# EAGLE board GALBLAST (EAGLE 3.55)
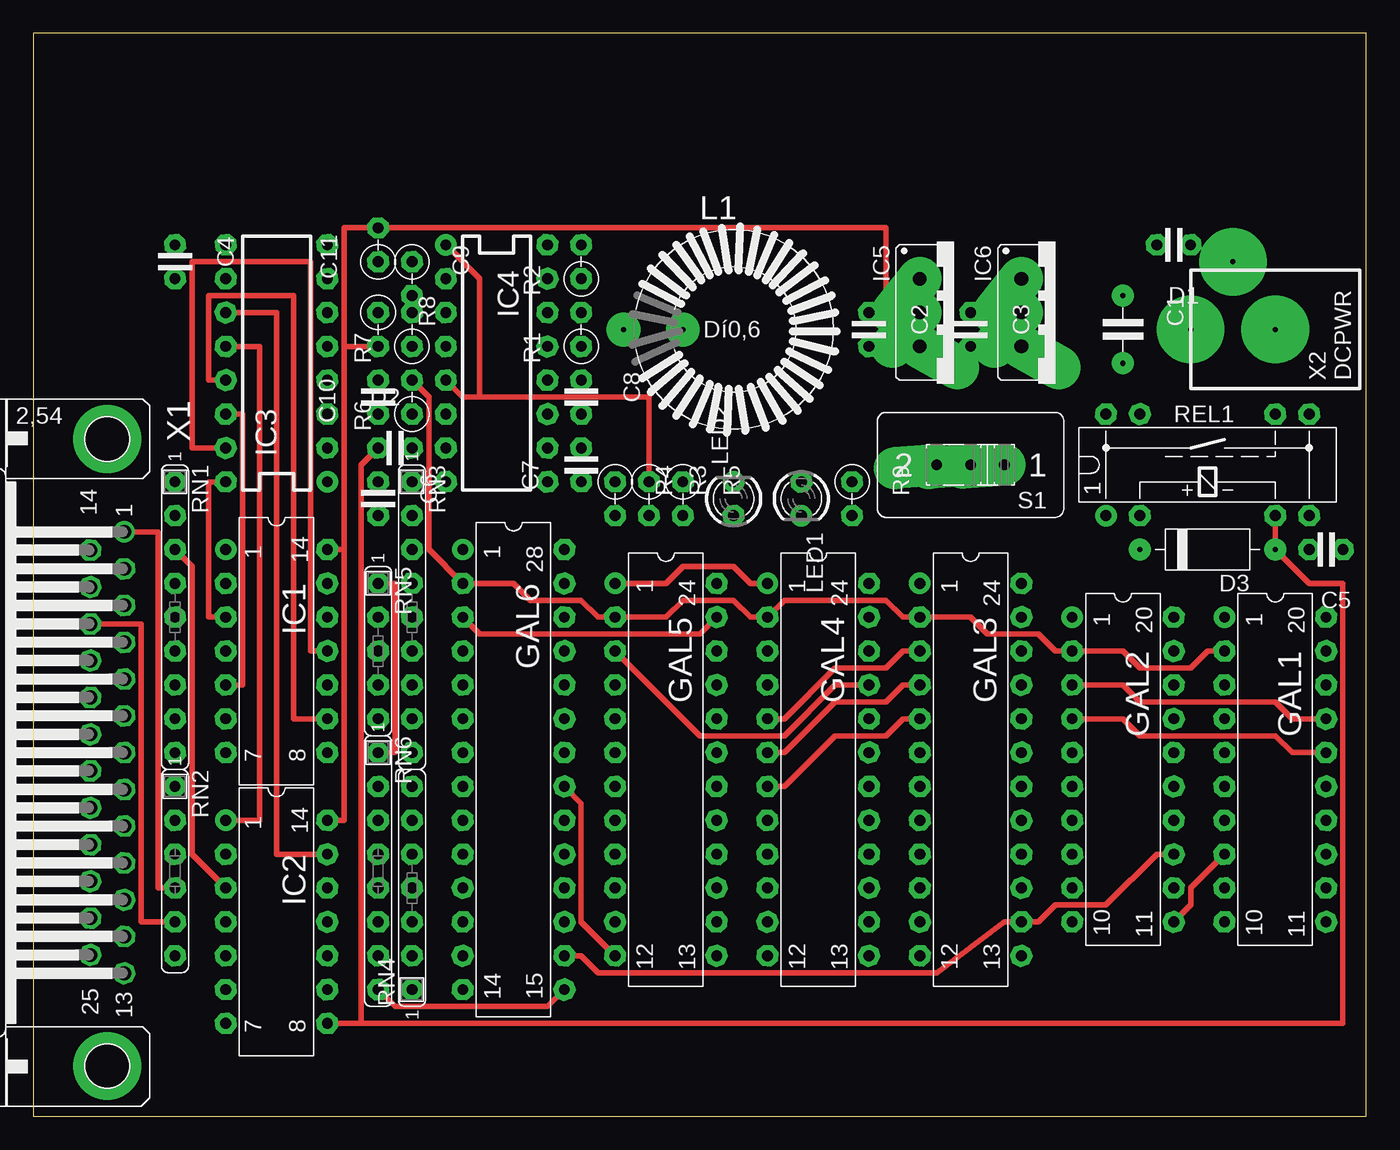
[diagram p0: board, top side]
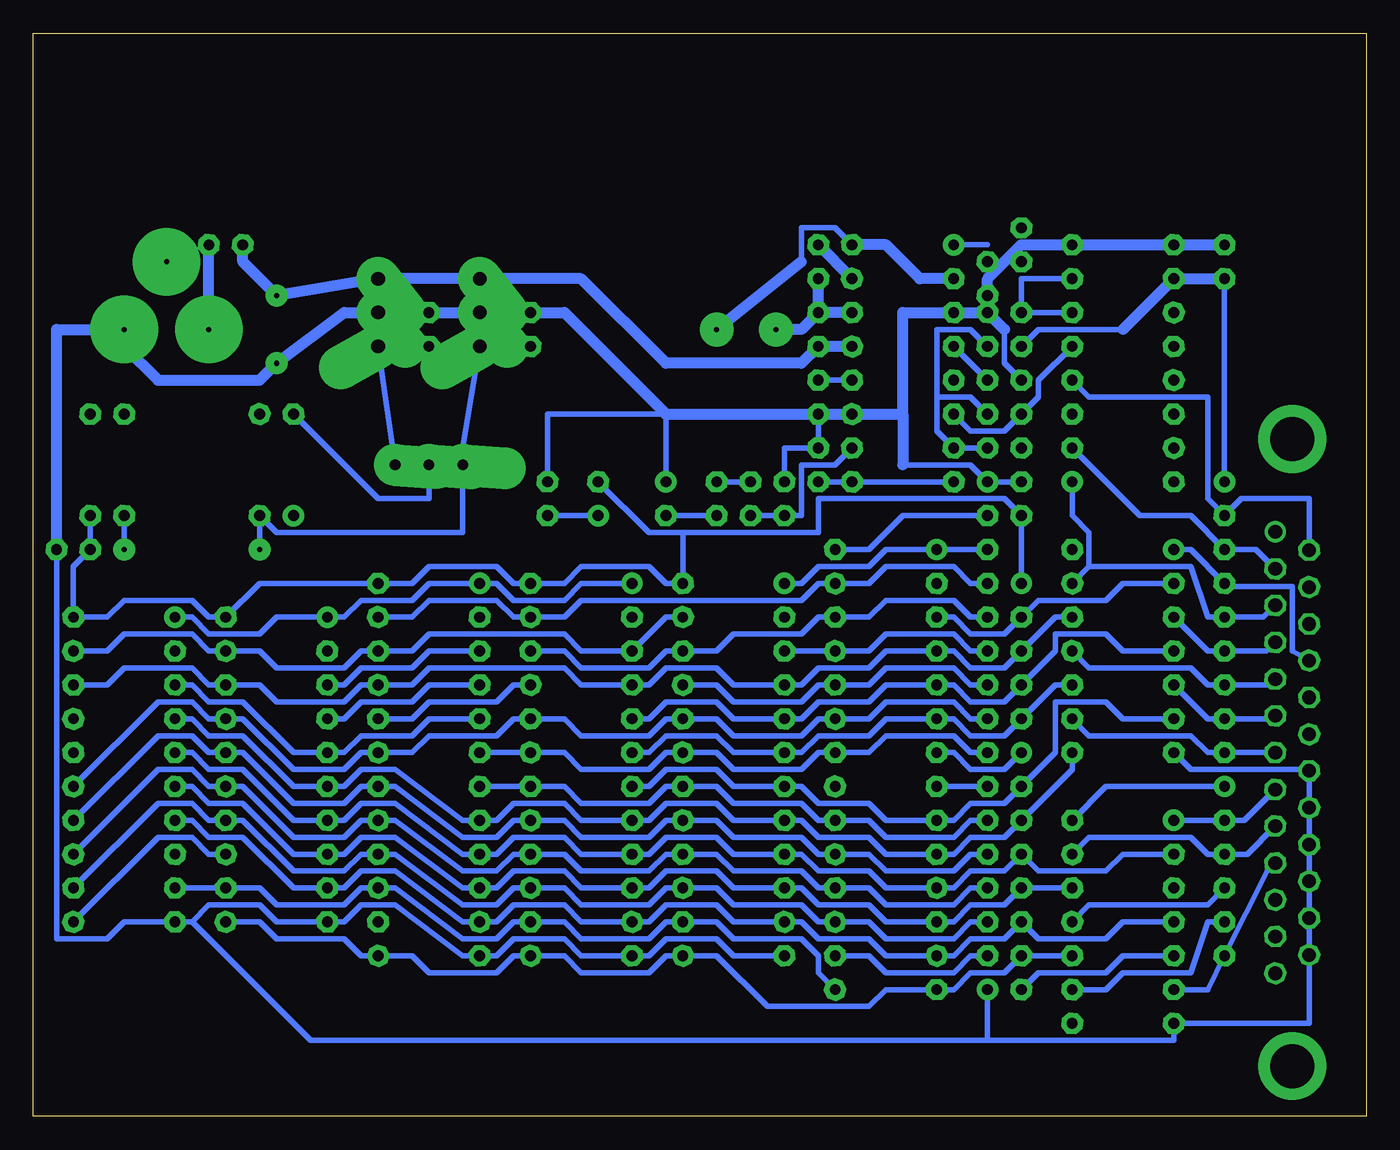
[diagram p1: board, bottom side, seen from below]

Size 100 x 81.27 mm. Coordinates in mm from the lower left corner, seen from the top.
Outline: 0,0 100,0 100,81.27 0,81.27 0,0
Copper layers used: Top, Bottom

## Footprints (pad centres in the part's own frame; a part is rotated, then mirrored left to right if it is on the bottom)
5 = drill 0.381 pad 1.651 round:  -2.54,0;  2.54,0
2,5 = drill 0.813 pad 1.6 octagon:  -1.27,0;  1.27,0
-2,5 = drill 0.813 pad 1.6 octagon:  0,0;  2.54,0
10 = drill 0.381 pad 1.651 round:  -5.08,0;  5.08,0
L20 = drill 0.813 pad 1.6 round:  -11.43,-3.81 | drill 0.813 pad 1.6 octagon:  -8.89,-3.81;  -6.35,-3.81;  -3.81,-3.81;  -1.27,-3.81;  1.27,-3.81;  3.81,-3.81;  6.35,-3.81;  8.89,-3.81;  11.43,-3.81;  11.43,3.81;  8.89,3.81;  6.35,3.81;  3.81,3.81;  1.27,3.81;  -1.27,3.81;  -3.81,3.81;  -6.35,3.81;  -8.89,3.81;  -11.43,3.81
L24-3 = drill 0.813 pad 1.6 round:  -13.97,-3.81 | drill 0.813 pad 1.6 octagon:  -11.43,-3.81;  -8.89,-3.81;  -6.35,-3.81;  -3.81,-3.81;  -1.27,-3.81;  1.27,-3.81;  3.81,-3.81;  6.35,-3.81;  8.89,-3.81;  11.43,-3.81;  13.97,-3.81;  13.97,3.81;  11.43,3.81;  8.89,3.81;  6.35,3.81;  3.81,3.81;  1.27,3.81;  -1.27,3.81;  -3.81,3.81;  -6.35,3.81;  -8.89,3.81;  -11.43,3.81;  -13.97,3.81
L28-3 = drill 0.813 pad 1.6 round:  -16.51,-3.81 | drill 0.813 pad 1.6 octagon:  -13.97,-3.81;  -11.43,-3.81;  -8.89,-3.81;  -6.35,-3.81;  -3.81,-3.81;  -1.27,-3.81;  1.27,-3.81;  3.81,-3.81;  6.35,-3.81;  8.89,-3.81;  11.43,-3.81;  13.97,-3.81;  16.51,-3.81;  16.51,3.81;  13.97,3.81;  11.43,3.81;  8.89,3.81;  6.35,3.81;  3.81,3.81;  1.27,3.81;  -1.27,3.81;  -3.81,3.81;  -6.35,3.81;  -8.89,3.81;  -11.43,3.81;  -13.97,3.81;  -16.51,3.81
L14 = drill 0.813 pad 1.6 round:  -7.62,-3.81 | drill 0.813 pad 1.6 octagon:  -5.08,-3.81;  -2.54,-3.81;  0,-3.81;  2.54,-3.81;  5.08,-3.81;  7.62,-3.81;  7.62,3.81;  5.08,3.81;  2.54,3.81;  0,3.81;  -2.54,3.81;  -5.08,3.81;  -7.62,3.81
L16 = drill 0.813 pad 1.6 round:  -8.89,-3.81 | drill 0.813 pad 1.6 octagon:  -6.35,-3.81;  -3.81,-3.81;  -1.27,-3.81;  1.27,-3.81;  3.81,-3.81;  6.35,-3.81;  8.89,-3.81;  8.89,3.81;  6.35,3.81;  3.81,3.81;  1.27,3.81;  -1.27,3.81;  -3.81,3.81;  -6.35,3.81;  -8.89,3.81
L16' = drill 0.813 pad 1.6 round:  -8.89,-3.81 | drill 0.813 pad 1.6 octagon:  -6.35,-3.81;  -1.27,-3.81;  -3.81,-3.81;  1.27,-3.81;  3.81,-3.81;  6.35,-3.81;  8.89,-3.81;  8.89,3.81;  6.35,3.81;  3.81,3.81;  1.27,3.81;  -1.27,3.81;  -3.81,3.81;  -6.35,3.81;  -8.89,3.81
XXS = drill 1.016 pad 3.251 offset:  -2.54,-2.54;  0,-2.54;  2.54,-2.54
16 = drill 0.381 pad 2.54 round:  -3.81,0;  -8.255,0
D3 = drill 0.813 pad 1.6 octagon:  -1.27,0 | drill 0.813 pad 1.6 round:  1.27,0
1A = drill 0.813 pad 1.6 round:  -7.62,-3.81 | drill 0.813 pad 1.6 octagon:  -5.08,-3.81;  5.08,-3.81;  7.62,-3.81;  7.62,3.81;  5.08,3.81;  -5.08,3.81;  -7.62,3.81
L9 = drill 0.813 pad 1.6 round:  -10.16,0 | drill 0.813 pad 1.6 octagon:  -7.62,0;  -5.08,0;  -2.54,0;  0,0;  2.54,0;  5.08,0;  7.62,0;  10.16,0
L6 = drill 0.813 pad 1.6 round:  -6.35,0 | drill 0.813 pad 1.6 octagon:  -3.81,0;  -1.27,0;  1.27,0;  3.81,0;  6.35,0
L7 = drill 0.813 pad 1.6 round:  -7.62,0 | drill 0.813 pad 1.6 octagon:  -5.08,0;  -2.54,0;  0,0;  2.54,0;  5.08,0;  7.62,0
L5 = drill 0.813 pad 1.6 round:  -5.08,0 | drill 0.813 pad 1.6 octagon:  -2.54,0;  0,0;  2.54,0;  5.08,0
L8 = drill 0.813 pad 1.6 round:  -8.89,0 | drill 0.813 pad 1.6 octagon:  -6.35,0;  -3.81,0;  -1.27,0;  1.27,0;  3.81,0;  6.35,0;  8.89,0
51 = drill 0.813 pad 3.15 offset:  -2.54,0;  0,0;  2.54,0
5HP = drill 1.016 pad 1.6 octagon:  16.561,1.27;  13.792,1.27;  11.049,1.27;  8.28,1.27;  5.512,1.27;  2.769,1.27;  0,1.27;  -2.769,1.27;  -5.512,1.27;  -8.28,1.27;  -11.049,1.27;  -13.792,1.27;  15.189,-1.27;  12.421,-1.27;  9.652,-1.27;  6.909,-1.27;  4.14,-1.27;  1.372,-1.27;  -1.372,-1.27;  -4.14,-1.27;  -6.909,-1.27;  -9.652,-1.27;  -12.421,-1.27;  -15.189,-1.27 | drill 1.016 pad 1.6 round:  -16.561,1.27 | drill 3.302 pad 5.08 round:  -23.52,0;  23.52,0
PWR = drill 0.381 pad 5.08 round:  0,2.54;  5.08,-0.635;  0,-3.81

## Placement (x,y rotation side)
C1  470u/16V  [5]  81.75,59.05 270 top
C2  100n  [2,5]  62.7,59.05 270 top
C3  100n  [2,5]  70.32,59.05 270 top
C4  100n  [2,5]  10.63,64.13 270 top
C5  100n  [2,5]  96.99,42.54 180 top
C6  100n  [2,5]  25.87,46.35 270 top
C7  100n  [2,5]  41.11,48.89 90 top
C8  10n  [2,5]  41.11,53.97 270 top
C9  100u/35V  [-2,5]  28.41,64.13 270 top
C10  4n7  [2,5]  25.87,53.97 90 top
C11  1u  [-2,5]  25.87,64.13 90 top
D1  1N4004  [2,5]  85.56,65.4 180 top
D2  1N4148  [2,5]  27.14,50.16 0 top
D3  1N4148  [10]  88.1,42.54 180 top
GAL1  18V10  [L20]  93.18,26.03 270 top
GAL2  16V8  [L20]  81.75,26.03 270 top
GAL3  20V8  [L24-3]  70.32,26.03 270 top
GAL4  V10/XV10/RA10  [L24-3]  58.89,26.03 270 top
GAL5  6001/6002  [L24-3]  47.46,26.03 270 top
GAL6  26V12  [L28-3]  36.03,26.03 270 top
IC1  7417  [L14]  18.25,34.92 270 top
IC2  7417  [L14]  18.25,14.6 270 top
IC3  ZN428E8  [L16]  18.25,56.51 90 top
IC4  78S40  [L16']  34.76,56.51 270 top
IC5  7805  [XXS]  69.05,60.32 270 top
IC6  LM3940-3.3  [XXS]  76.67,60.32 270 top
L1  470uH  [16]  52.54,59.05 0 top
LED1  LED3YE  [D3]  57.62,46.35 270 top
LED2  LED3GR  [D3]  52.54,46.35 90 top
R1  1R2  [-2,5]  41.11,57.78 90 top
R2  180R  [-2,5]  41.11,62.86 90 top
R3  220k  [-2,5]  46.19,47.62 270 top
R4  12k  [-2,5]  43.65,47.62 270 top
R5  4k7  [-2,5]  48.73,47.62 270 top
R6  100k  [-2,5]  28.41,52.7 90 top
R7  12k  [-2,5]  28.41,57.78 90 top
R8  390R  [-2,5]  25.87,60.32 270 top
R9  820R  [-2,5]  61.43,47.62 270 top
REL1  RR1A  [1A]  88.1,48.89 0 top
RN1  4k7  [L9]  10.63,37.46 270 top
RN2  4k7  [L6]  10.63,18.41 270 top
RN3  4k7  [L9]  28.41,37.46 270 top
RN4  4k7  [L7]  28.41,17.14 90 top
RN5  4k7  [L5]  25.87,34.92 270 top
RN6  4k7  [L8]  25.87,18.41 270 top
S1  Sw1  [51]  70.32,48.89 180 top
X1  M25HP  [5HP]  5.55,27.3 270 top
X2  DCPWR  [PWR]  89.37,59.05 90 top

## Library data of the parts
C1-C11 D1-D3 R1-R9 = DISCRETE
GAL1-GAL6 = DIL
IC1 IC2 = 74XX
IC3 = ferranti
IC4-IC6 = V-REG
L1 = IND-A
LED1 LED2 = LED
REL1 = RELAIS
RN1-RN6 = R-SIL
S1 = SWITCH
X1 = SUBD-A
X2 = SPECIAL

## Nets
/ACK: IC2. RN2. X1.
/STB: GAL1. GAL2. GAL3. GAL4. GAL5. GAL6. IC2. RN6.
/STROBE: IC2. RN2. X1.
D0: IC2. IC3. RN1. X1.
D1: IC1. IC3. RN1. X1.
D2: IC1. IC3. RN1. X1.
D3: IC1. IC3. RN1. X1.
D4: IC1. IC3. RN1. X1.
D5: IC1. IC3. RN1. X1.
D6: IC2. IC3. RN2. X1.
D7: IC2. IC3. RN2. X1.
EDIT: GAL1. GAL2. GAL3. GAL4. GAL5. GAL6. IC4. R6.
N$1: IC3. RN1. X1.
N$2: D1. X2.
N$3: IC1. RN1. X1.
N$4: IC2. RN2. X1.
N$5: C7. IC4.
N$6: LED2. R5.
N$7: C8. IC4.
N$8: REL1. S1.
N$9: GAL6. RN4.
N$10: GAL3. GAL4. GAL5. GAL6. RN3.
N$11: IC4. R3. R4.
N$12: LED1. R9.
N$13: IC4. L1. R1. R2.
N$14: IC4. R2.
N$15: GAL5. GAL6. RN3.
N$16: GAL1. GAL2. GAL3. GAL4. GAL5. GAL6. RN3.
N$17: IC4. L1.
N$18: C9. IC4. R3. R5.
N$19: C1. C2. C3. C4. C5. C6. C7. C8. C9. C10. C11. GAL1. GAL2. GAL3. GAL4. GAL5. GAL6. IC1. IC2. IC3. IC4. IC5. IC6. LED2. R4. R7. R9. RN3. RN4. X1. X2.
N$20: C1. D1. IC4. IC5. IC6. R1.
N$21: C11. IC3. R8.
N$22: GAL3. GAL4. GAL5. GAL6. RN3.
N$23: D2. IC4. R6. R7.
N$24: GAL3. GAL4. GAL5. GAL6. RN4.
N$25: GAL1. GAL2. GAL3. GAL4. GAL5. GAL6. RN4.
N$26: GAL1. GAL2. GAL3. GAL4. GAL5. GAL6. RN4.
N$27: C2. C4. D3. IC1. IC2. IC3. IC5. R8. REL1. RN1. RN2. S1.
N$28: GAL1. GAL2. GAL3. GAL4. GAL5. GAL6. RN4.
N$29: GAL1. GAL2. GAL3. GAL6. RN4.
N$30: GAL6. RN3.
N$31: GAL1. GAL2. GAL3. GAL4. GAL5. GAL6. RN3.
N$32: GAL4. GAL5. GAL6. RN3.
N$33: GAL3. GAL4. GAL6. RN3.
N$35: C10. IC3. IC4.
N$36: D2. D3. IC2. REL1.
P/V: GAL1. GAL2. GAL3. GAL4. GAL5. GAL6. IC1. RN5.
RA0: GAL1. GAL2. GAL3. GAL4. GAL5. GAL6. IC1. RN5.
RA1: GAL1. GAL2. GAL3. GAL4. GAL5. GAL6. IC1. RN5.
RA2: GAL1. GAL2. GAL3. GAL4. GAL5. GAL6. IC1. RN5.
RA3: GAL1. GAL2. GAL3. GAL4. GAL5. GAL6. IC1. RN6.
RA4: GAL1. GAL2. GAL3. GAL4. GAL5. GAL6. IC1. RN6.
RA5: GAL1. GAL2. GAL3. GAL4. GAL5. GAL6. IC2. RN6.
SCHALT: X2.
SCLK: GAL1. GAL2. GAL3. GAL4. GAL5. GAL6. IC2. RN6.
SDIN: GAL1. GAL2. GAL3. GAL4. GAL5. GAL6. IC2. RN6.
SDOUT: GAL1. GAL2. GAL3. GAL4. GAL5. GAL6. IC2. RN6.
SW1: C3. IC6. S1.
VCC: C5. C6. GAL1. GAL2. GAL3. GAL4. GAL5. GAL6. LED1. REL1. RN5. RN6.

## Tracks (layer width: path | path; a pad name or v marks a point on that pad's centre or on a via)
/ACK
  Bottom 0.406: 6.82,19.02 7.43,18.41 RN2. 11.9,9.52 14.44,9.52
/STB
  Top 0.406: 89.37,19.68 86.83,17.14 86.83,15.87 85.56,14.6
  Bottom 0.406: 85.56,14.6 83.02,14.6 81.75,13.33 76.67,13.33 75.4,12.06 74.13,12.06 71.59,12.06 70.32,10.79 65.24,10.79 63.97,12.06 62.7,12.06 60.16,12.06 58.89,10.79 53.81,10.79 52.54,12.06 51.27,12.06 48.73,12.06 44.92,8.25 37.3,8.25 36.03,9.52 32.22,9.52 30.95,9.52 29.68,10.79 27.14,10.79 25.87,12.06 22.06,12.06
/STROBE
  Top 0.406: 6.82,43.86 9.36,43.86 9.36,17.14 10.63,17.14
  Bottom 0.406: 10.63,17.14 11.9,15.87 20.79,15.87 22.06,14.6
D0
  Top 0.406: 14.44,17.14 11.9,19.68 11.9,41.27 10.63,42.54
  Bottom 0.406: 6.82,41.09 8.27,42.54 10.63,42.54 13.17,45.08 16.98,45.08 22.06,50.16
D1
  Bottom 0.406: 6.82,38.35 7.71,37.46 10.63,37.46 11.9,37.46 13.17,41.27 20.79,41.27 | 22.06,47.62 22.06,45.08 20.79,43.81 20.79,41.27 | 20.79,41.27 22.06,40
D2
  Top 0.406: IC3. 13.17,47.62 13.17,37.46 14.44,37.46
  Bottom 0.406: 6.82,35.58 7.48,34.92 10.63,34.92 11.9,34.92 14.44,37.46
D3
  Top 0.406: 14.44,50.16 11.9,50.16 11.9,64.13 20.79,64.13 20.79,34.92 22.06,34.92
  Bottom 0.406: 6.82,32.81 7.25,32.38 10.63,32.38 11.9,32.38 13.17,33.65 20.79,33.65 22.06,34.92
D4
  Top 0.406: 14.44,52.7 15.71,52.7 15.71,32.38 14.44,32.38
  Bottom 0.406: 6.82,30.07 7.05,29.84 10.63,29.84 11.9,29.84 14.44,32.38
D5
  Top 0.406: 14.44,55.24 13.17,55.24 13.17,61.59 19.52,61.59 19.52,29.84 22.06,29.84
  Bottom 0.406: 6.82,27.3 RN1. 11.9,27.3 13.17,28.57 20.79,28.57 22.06,29.84
D6
  Top 0.406: 14.44,22.22 16.98,22.22 16.98,57.78 14.44,57.78
  Bottom 0.406: 6.82,24.53 9.13,22.22 10.63,22.22 14.44,22.22
D7
  Top 0.406: 14.44,60.32 18.25,60.32 18.25,19.68 22.06,19.68
  Bottom 0.406: 6.82,21.79 8.93,19.68 10.63,19.68 11.9,19.68 13.17,20.95 20.79,20.95 22.06,19.68
EDIT
  Top 0.406: 89.37,34.92 88.1,34.92 86.83,33.65 83.02,33.65 81.75,34.92 77.94,34.92 76.67,34.92 75.4,36.19 71.59,36.19 70.32,37.46 66.51,37.46 65.24,37.46 63.97,38.73 56.35,38.73 55.08,37.46 53.81,37.46 52.54,38.73 48.73,38.73 47.46,37.46 43.65,37.46 42.38,37.46 41.11,38.73 37.3,38.73 36.03,40 32.22,40 29.68,42.54 29.68,53.97 R6.
  Bottom 0.406: R6. 30.95,57.78
N$1
  Bottom 0.406: 4.28,42.49 4.28,46.35 9.36,46.35 10.63,45.08 11.9,46.35 11.9,53.97 20.79,53.97 22.06,55.24
N$2
  Bottom 0.813: 86.83,59.05 86.83,65.4
N$3
  Bottom 0.406: 4.28,34.21 5.55,34.92 5.55,39.75 10.38,39.75 10.63,40 13.17,42.54 14.44,42.54
N$4
  Top 0.406: 10.63,14.6 8.09,14.6 8.09,36.95 4.28,36.95
  Bottom 0.406: 10.63,14.6 11.9,14.6 13.17,10.79 18.25,10.79 19.52,9.52 22.06,9.52
N$5
  Bottom 0.406: 30.95,47.62 38.57,47.62 41.11,47.62
N$6
  Bottom 0.406: R5. 52.54,45.08
N$7
  Bottom 0.406: 38.57,55.24 41.11,55.24
N$8
  Bottom 0.406: 70.32,48.89 70.32,46.35 74.13,46.35 REL1.
N$9
  Bottom 0.406: RN4. 32.22,24.76
N$10
  Top 0.406: 62.7,32.38 60.16,32.38 56.35,28.57 50,28.57 43.65,34.92
  Bottom 0.406: 43.65,34.92 39.84,34.92 37.3,34.92 36.03,36.19 30.95,36.19 29.68,34.92 28.41,34.92 | 62.7,32.38 63.97,32.38 65.24,31.11 70.32,31.11 71.59,29.84 74.13,29.84
N$11
  Bottom 0.406: 38.57,50.16 39.84,48.89 42.38,48.89 42.38,46.35 42.38,45.08 R4. R3.
N$12
  Bottom 0.406: LED1. R9.
N$13
  Bottom 0.813: 38.57,60.32 R1. | R1. 41.11,62.86 | R1. 42.38,59.05 L1.
N$14
  Bottom 0.813: 38.57,62.86 R2.
N$15
  Bottom 0.406: 51.27,32.38 48.73,32.38 47.46,31.11 42.38,31.11 41.11,32.38 39.84,32.38 37.3,32.38 36.03,33.65 30.95,33.65 29.68,32.38 28.41,32.38
N$16
  Bottom 0.406: 28.41,29.84 29.68,29.84 30.95,31.11 36.03,31.11 37.3,29.84 39.84,29.84 41.11,29.84 42.38,28.57 47.46,28.57 48.73,29.84 51.27,29.84 52.54,29.84 53.81,28.57 58.89,28.57 60.16,29.84 62.7,29.84 63.97,29.84 65.24,28.57 70.32,28.57 71.59,27.3 74.13,27.3 75.4,27.3 76.67,26.03 80.48,26.03 84.29,29.84 85.56,29.84 86.83,29.84 88.1,31.11 90.64,31.11 96.99,24.76
N$17
  Bottom 0.406: IC4. 39.84,66.67 42.38,66.67 42.38,64.13
  Bottom 0.813: 30.95,62.86 33.49,62.86 36.03,65.4 IC4. | 42.38,64.13 48.73,59.05
N$18
  Top 0.406: 46.19,47.62 46.19,53.97 33.49,53.97 | 33.49,53.97 32.22,53.97 30.95,55.24 | 30.95,65.4 33.49,62.86 33.49,53.97
  Bottom 0.406: 30.95,65.4 28.41,65.4 | 46.19,47.62 48.73,47.62
N$19
  Top 0.406: 39.84,24.76 41.11,23.49 41.11,14.6 43.65,12.06
  Bottom 0.406: 43.65,12.06 47.46,12.06 48.73,13.33 52.54,13.33 53.81,12.06 55.08,12.06 58.89,12.06 60.16,13.33 63.97,13.33 65.24,12.06 66.51,12.06 67.78,12.06 72.86,15.87 75.4,15.87 76.67,14.6 77.94,14.6 81.75,14.6 83.02,15.87 86.83,15.87 88.1,14.6 | 10.63,65.4 14.44,65.4 22.06,65.4 25.87,65.4 | 28.41,47.62 25.87,47.62 28.41,47.62 | 88.1,14.6 89.37,14.6 93.18,14.6 94.45,13.33 98.26,13.33 98.26,42.54 | 28.41,5.71 14.44,5.71 14.44,6.98 4.28,6.98 4.28,12.11 4.28,26.03 13.17,26.03 14.44,27.3 | 28.41,5.71 28.41,9.52 | 28.41,5.71 79.21,5.71 88.1,14.6 | C7. C8. C7. | C10. 27.14,56.51 27.14,59.05 | C7. 43.65,50.16 43.65,47.62 | 28.41,47.62 29.68,48.89 34.76,48.89 | 61.43,47.62 61.43,52.7 52.54,52.7 LED2.
  Bottom 0.813: 10.63,65.4 14.44,65.4 22.06,65.4 25.87,65.4 28.41,62.86 R7. | R7. 30.95,60.32 34.76,60.32 34.76,52.7 | R7. 27.14,59.05 | 34.76,52.7 38.57,52.7 C8. 52.54,52.7 60.16,60.32 62.7,60.32 66.51,60.32 70.32,60.32 74.13,60.32 76.67,60.32 C1. 83.02,55.24 90.64,55.24 93.18,57.78 X2. 98.26,59.05 98.26,42.54 | 34.76,52.7 34.76,48.89
N$20
  Bottom 0.813: 38.57,57.78 41.11,57.78 42.38,56.51 52.54,56.51 58.89,62.86 66.51,62.86 74.13,62.86 81.75,61.59 84.29,64.13 D1.
N$21
  Bottom 0.406: 22.06,62.86 25.87,62.86 25.87,60.32 22.06,60.32
N$22
  Bottom 0.406: 66.51,27.3 62.7,27.3 60.16,27.3 58.89,26.03 53.81,26.03 52.54,27.3 51.27,27.3 48.73,27.3 47.46,26.03 42.38,26.03 41.11,27.3 39.84,27.3 37.3,27.3 36.03,28.57 30.95,28.57 29.68,27.3 RN3.
N$23
  Bottom 0.406: 28.41,52.7 29.68,53.97 32.22,53.97 | 32.22,53.97 32.22,51.43 30.95,50.16 D2. | 28.41,57.78 29.68,59.05 32.22,59.05 32.22,53.97
N$24
  Bottom 0.406: 66.51,24.76 62.7,24.76 60.16,24.76 58.89,23.49 53.81,23.49 52.54,24.76 51.27,24.76 48.73,24.76 47.46,23.49 42.38,23.49 41.11,22.22 39.84,22.22 37.3,22.22 36.03,20.95 30.95,20.95 29.68,22.22 28.41,22.22
N$25
  Bottom 0.406: 28.41,19.68 29.68,19.68 30.95,18.41 36.03,18.41 37.3,19.68 39.84,19.68 41.11,19.68 42.38,20.95 47.46,20.95 48.73,22.22 51.27,22.22 52.54,22.22 53.81,20.95 58.89,20.95 60.16,22.22 62.7,22.22 63.97,22.22 65.24,20.95 67.78,20.95 72.86,24.76 74.13,24.76 75.4,24.76 76.67,23.49 80.48,23.49 84.29,27.3 85.56,27.3 86.83,27.3 88.1,28.57 90.64,28.57 96.99,22.22
N$26
  Bottom 0.406: 28.41,17.14 29.68,17.14 30.95,15.87 36.03,15.87 37.3,17.14 39.84,17.14 41.11,17.14 42.38,18.41 47.46,18.41 48.73,19.68 51.27,19.68 52.54,19.68 53.81,18.41 58.89,18.41 60.16,19.68 62.7,19.68 63.97,19.68 65.24,18.41 67.78,18.41 72.86,22.22 74.13,22.22 75.4,22.22 76.67,20.95 80.48,20.95 84.29,24.76 85.56,24.76 86.83,24.76 88.1,26.03 90.64,26.03 96.99,19.68
N$27
  Top 0.406: 23.33,42.54 23.33,57.78 | 23.33,42.54 IC1. | 23.33,42.54 23.33,22.22 IC2. | 23.33,57.78 23.33,66.67 63.97,66.67 63.97,59.05 65.24,57.78 IC5. | 23.33,57.78 R8.
  Bottom 0.406: C4. 10.63,47.62 | R8. 24.6,59.05 18.25,59.05 | IC2. 19.52,24.76 10.63,24.76 | D3. 83.02,45.08 81.75,43.81 67.78,43.81 S1. 67.78,50.16 IC5. C2.
  Bottom 0.813: C4. 14.44,62.86 18.25,59.05
N$28
  Bottom 0.406: 28.41,14.6 29.68,14.6 30.95,13.33 36.03,13.33 37.3,14.6 39.84,14.6 41.11,14.6 42.38,15.87 47.46,15.87 48.73,17.14 51.27,17.14 52.54,17.14 53.81,15.87 58.89,15.87 60.16,17.14 62.7,17.14 63.97,17.14 65.24,15.87 67.78,15.87 72.86,19.68 74.13,19.68 75.4,19.68 76.67,18.41 80.48,18.41 84.29,22.22 85.56,22.22 86.83,22.22 88.1,23.49 90.64,23.49 96.99,17.14
N$29
  Top 0.406: 39.84,12.06 41.11,12.06 42.38,10.79 67.78,10.79 72.86,14.6 74.13,14.6 75.4,14.6 76.67,15.87 80.48,15.87 84.29,19.68 85.56,19.68
  Bottom 0.406: 39.84,12.06 37.3,12.06 36.03,10.79 30.95,10.79 29.68,12.06 28.41,12.06 | 96.99,14.6 90.64,20.95 88.1,20.95 86.83,19.68 85.56,19.68
N$30
  Bottom 0.406: GAL6. 37.3,42.54 34.76,45.08 28.41,45.08
N$31
  Top 0.406: 43.65,40 47.46,40 48.73,41.27 52.54,41.27 53.81,40 55.08,40
  Bottom 0.406: 43.65,40 42.38,40 41.11,41.27 37.3,41.27 36.03,42.54 32.22,42.54 28.41,42.54 | 89.37,37.46 88.1,37.46 86.83,36.19 83.02,36.19 81.75,37.46 77.94,37.46 76.67,37.46 75.4,38.73 71.59,38.73 70.32,40 66.51,40 65.24,40 63.97,38.73 60.16,38.73 58.89,40 55.08,40
N$32
  Bottom 0.406: 62.7,34.92 60.16,34.92 58.89,33.65 53.81,33.65 52.54,34.92 51.27,34.92 48.73,34.92 47.46,36.19 42.38,36.19 41.11,37.46 39.84,37.46 37.3,37.46 36.03,38.73 30.95,38.73 29.68,37.46 28.41,37.46
N$33
  Bottom 0.406: 74.13,37.46 71.59,37.46 70.32,38.73 65.24,38.73 63.97,37.46 62.7,37.46 60.16,37.46 58.89,38.73 42.38,38.73 41.11,40 39.84,40 37.3,40 36.03,41.27 30.95,41.27 29.68,40 28.41,40
N$35
  Bottom 0.406: 22.06,57.78 24.6,55.24 24.6,53.97 25.87,52.7 27.14,51.43 29.68,51.43 30.95,52.7
N$36
  Top 0.406: 22.06,6.98 24.6,6.98 | 24.6,6.98 98.26,6.98 98.26,40 95.72,40 93.18,42.54 93.18,45.08 | 25.87,50.16 24.6,48.89 24.6,6.98
  Bottom 0.406: 93.18,42.54 93.18,45.08
P/V
  Top 0.406: 51.27,37.46 50,36.19 33.49,36.19 32.22,37.46
  Bottom 0.406: 51.27,37.46 52.54,37.46 55.08,34.92 58.89,34.92 60.16,36.19 70.32,36.19 71.59,34.92 74.13,34.92 75.4,34.92 76.67,33.65 81.75,33.65 83.02,34.92 85.56,34.92 86.83,34.92 88.1,36.19 93.18,36.19 94.45,34.92 96.99,34.92 | 32.22,37.46 30.95,37.46 29.68,36.19 27.14,36.19 25.87,37.46 24.6,38.73 19.52,38.73 18.25,40 14.44,40
RA0
  Bottom 0.406: 96.99,32.38 94.45,32.38 93.18,33.65 88.1,33.65 86.83,32.38 85.56,32.38 83.02,32.38 81.75,31.11 76.67,31.11 75.4,32.38 74.13,32.38 71.59,32.38 70.32,33.65 60.16,33.65 58.89,32.38 55.08,32.38 53.81,32.38 52.54,33.65 48.73,33.65 47.46,32.38 43.65,32.38 42.38,32.38 41.11,33.65 37.3,33.65 36.03,34.92 32.22,34.92 30.95,34.92 29.68,33.65 27.14,33.65 25.87,34.92 23.33,37.46 22.06,37.46
RA1
  Top 0.406: 77.94,32.38 81.75,32.38 83.02,31.11 93.18,31.11 94.45,29.84 96.99,29.84 | 55.08,29.84 56.35,29.84 60.16,33.65 63.97,33.65 65.24,34.92 66.51,34.92
  Bottom 0.406: 55.08,29.84 53.81,29.84 52.54,31.11 48.73,31.11 47.46,29.84 43.65,29.84 42.38,29.84 41.11,31.11 37.3,31.11 36.03,32.38 32.22,32.38 30.95,32.38 29.68,31.11 27.14,31.11 25.87,32.38 23.33,34.92 23.33,36.19 19.52,36.19 18.25,34.92 14.44,34.92 | 66.51,34.92 70.32,34.92 71.59,33.65 75.4,33.65 76.67,32.38 77.94,32.38
RA2
  Top 0.406: 77.94,29.84 81.75,29.84 83.02,28.57 93.18,28.57 94.45,27.3 96.99,27.3 | 55.08,27.3 56.35,27.3 60.16,31.11 63.97,31.11 65.24,32.38 66.51,32.38
  Bottom 0.406: 55.08,27.3 53.81,27.3 52.54,28.57 48.73,28.57 47.46,27.3 43.65,27.3 42.38,27.3 41.11,28.57 37.3,28.57 36.03,29.84 32.22,29.84 30.95,29.84 29.68,28.57 27.14,28.57 RN5. 23.33,32.38 22.06,32.38 | 66.51,32.38 70.32,32.38 71.59,31.11 75.4,31.11 76.67,29.84 77.94,29.84
RA3
  Top 0.406: 55.08,24.76 56.35,24.76 60.16,28.57 63.97,28.57 65.24,29.84 66.51,29.84
  Bottom 0.406: 55.08,24.76 53.81,24.76 52.54,26.03 48.73,26.03 47.46,24.76 43.65,24.76 42.38,24.76 41.11,23.49 37.3,23.49 36.03,22.22 32.22,22.22 30.95,22.22 29.68,23.49 27.14,23.49 25.87,24.76 23.33,27.3 23.33,31.11 19.52,31.11 18.25,29.84 14.44,29.84 | 89.37,32.38 88.1,32.38 86.83,31.11 84.29,31.11 80.48,27.3 77.94,27.3 76.67,27.3 75.4,28.57 71.59,28.57 70.32,29.84 66.51,29.84
RA4
  Bottom 0.406: 89.37,29.84 88.1,29.84 86.83,28.57 84.29,28.57 80.48,24.76 77.94,24.76 76.67,24.76 75.4,26.03 72.86,26.03 67.78,22.22 66.51,22.22 65.24,22.22 63.97,23.49 60.16,23.49 58.89,22.22 55.08,22.22 53.81,22.22 52.54,23.49 48.73,23.49 47.46,22.22 43.65,22.22 42.38,22.22 41.11,20.95 37.3,20.95 36.03,19.68 32.22,19.68 30.95,19.68 29.68,20.95 27.14,20.95 25.87,22.22 22.06,26.03 22.06,27.3
RA5
  Bottom 0.406: 89.37,27.3 88.1,27.3 86.83,26.03 84.29,26.03 80.48,22.22 77.94,22.22 76.67,22.22 75.4,23.49 72.86,23.49 67.78,19.68 66.51,19.68 65.24,19.68 63.97,20.95 60.16,20.95 58.89,19.68 55.08,19.68 53.81,19.68 52.54,20.95 48.73,20.95 47.46,19.68 43.65,19.68 42.38,19.68 41.11,18.41 37.3,18.41 36.03,17.14 32.22,17.14 30.95,17.14 29.68,18.41 27.14,18.41 25.87,19.68 24.6,18.41 19.52,18.41 18.25,19.68 14.44,19.68
SCLK
  Bottom 0.406: 89.37,24.76 88.1,24.76 86.83,23.49 84.29,23.49 80.48,19.68 77.94,19.68 76.67,19.68 75.4,20.95 72.86,20.95 67.78,17.14 66.51,17.14 65.24,17.14 63.97,18.41 60.16,18.41 58.89,17.14 55.08,17.14 53.81,17.14 52.54,18.41 48.73,18.41 47.46,17.14 43.65,17.14 42.38,17.14 41.11,15.87 37.3,15.87 36.03,14.6 32.22,14.6 30.95,14.6 29.68,15.87 27.14,15.87 25.87,17.14 22.06,17.14
SDIN
  Bottom 0.406: 89.37,22.22 88.1,22.22 86.83,20.95 84.29,20.95 80.48,17.14 77.94,17.14 76.67,17.14 75.4,18.41 72.86,18.41 67.78,14.6 66.51,14.6 65.24,14.6 63.97,15.87 60.16,15.87 58.89,14.6 55.08,14.6 53.81,14.6 52.54,15.87 48.73,15.87 47.46,14.6 43.65,14.6 42.38,14.6 41.11,13.33 37.3,13.33 36.03,12.06 32.22,12.06 30.95,12.06 29.68,13.33 27.14,13.33 25.87,14.6 24.6,13.33 19.52,13.33 18.25,14.6 14.44,14.6
SDOUT
  Top 0.406: RN6. 27.14,8.25 38.57,8.25 39.84,9.52
  Bottom 0.406: 89.37,17.14 85.56,17.14 83.02,17.14 81.75,15.87 76.67,15.87 75.4,17.14 74.13,17.14 72.86,17.14 67.78,13.33 65.24,13.33 63.97,14.6 62.7,14.6 60.16,14.6 58.89,13.33 53.81,13.33 52.54,14.6 51.27,14.6 48.73,14.6 47.46,13.33 42.38,13.33 41.11,12.06 41.11,10.79 39.84,9.52 | 14.44,12.06 18.25,12.06 19.52,10.79 24.6,10.79 RN6.
SW1
  Bottom 0.406: C3. IC6. 72.86,48.89
VCC
  Top 0.406: 25.87,27.3 27.14,27.3 27.14,40 25.87,40
  Bottom 0.406: 25.87,40 C6. 27.14,46.35 41.11,46.35 41.11,43.81 51.27,43.81 | 25.87,27.3 27.14,26.03 29.68,26.03 30.95,27.3 32.22,27.3 | 51.27,43.81 GAL5. 52.54,40 53.81,41.27 58.89,41.27 60.16,40 GAL4. 63.97,40 65.24,41.27 70.32,41.27 71.59,40 GAL3. 83.02,40 GAL2. 86.83,37.46 88.1,38.73 93.18,38.73 94.45,37.46 GAL1. 96.99,41.27 C5. 95.72,45.08 | 51.27,43.81 53.81,43.81 57.62,47.62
